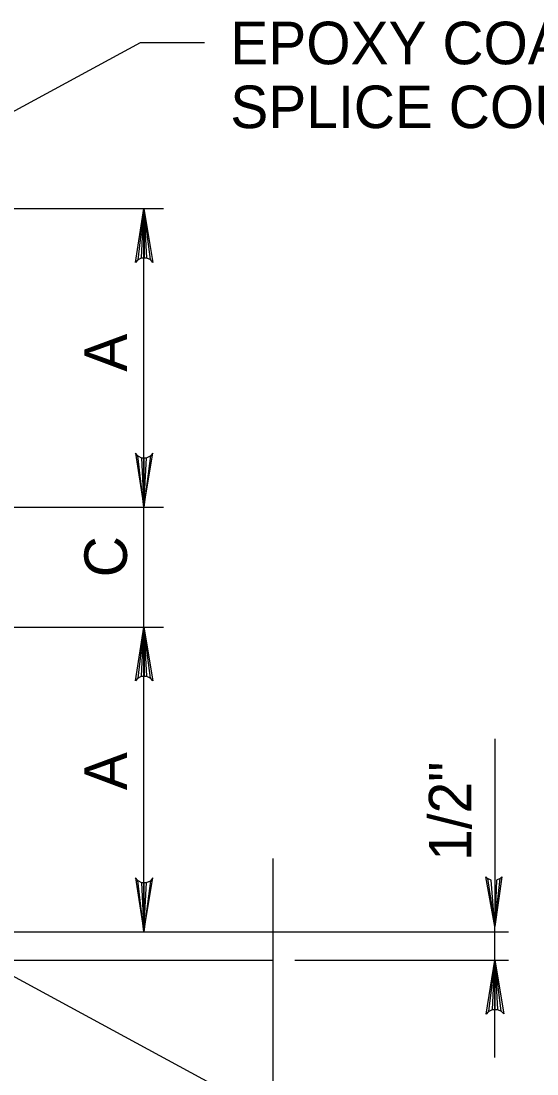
# Model space of a CAD drawing. Extents: x 641328 to 643024, y 298283 to 300065.
# Drawn here: x 641815.4 to 641851.7, y 298994.6 to 299068.8 of the extents above; entities that cross this region are included whole.
import ezdxf

# ---------------------------------------------------------------- set-up
doc = ezdxf.new("R2010")
doc.units = 0
doc.layers.add('2', color=7, linetype='Continuous')
doc.layers.add('40', color=7, linetype='Continuous')

msp = doc.modelspace()

# ---------------------------------------------------------------- linework, layer by layer
at = {"layer": '2'}
for p, q in [((641804.734, 299055.572), (641825.398, 299055.572)), ((641823.433, 299051.77), (641824.023, 299055.572)), ((641824.023, 299055.572), (641823.593, 299051.963)), ((641823.858, 299052.099), (641824.023, 299055.572)), ((641824.023, 299034.542), (641824.023, 299055.572)), ((641824.023, 299055.572), (641824.219, 299052.101)), ((641824.481, 299051.974), (641824.023, 299055.572)), ((641824.023, 299055.572), (641824.658, 299051.778)), ((641824.023, 299055.572), (641824.039, 299052.1)), ((641823.593, 299051.963), (641823.433, 299051.77)), ((641823.593, 299051.963), (641823.858, 299052.099)), ((641823.858, 299052.099), (641824.219, 299052.101)), ((641824.219, 299052.101), (641824.481, 299051.974)), ((641824.658, 299051.778), (641824.481, 299051.974)), ((641823.593, 299038.151), (641823.433, 299038.344)), ((641823.433, 299038.344), (641824.023, 299034.542)), ((641823.593, 299038.151), (641823.858, 299038.015)), ((641824.023, 299034.542), (641823.593, 299038.151)), ((641823.858, 299038.015), (641824.023, 299034.542)), ((641823.858, 299038.015), (641824.219, 299038.013)), ((641824.023, 299034.542), (641824.658, 299038.336)), ((641824.481, 299038.14), (641824.023, 299034.542)), ((641824.023, 299034.542), (641824.039, 299038.014)), ((641824.023, 299034.542), (641824.219, 299038.013)), ((641824.219, 299038.013), (641824.481, 299038.14)), ((641824.658, 299038.336), (641824.481, 299038.14)), ((641801.889, 299034.542), (641825.398, 299034.542)), ((641824.023, 299026.087), (641824.023, 299034.542)), ((641801.889, 299026.087), (641825.398, 299026.087)), ((641823.433, 299022.285), (641824.023, 299026.087)), ((641824.023, 299026.087), (641823.593, 299022.477)), ((641823.858, 299022.613), (641824.023, 299026.087)), ((641824.023, 299004.614), (641824.023, 299026.087)), ((641824.023, 299026.087), (641824.219, 299022.616)), ((641824.481, 299022.488), (641824.023, 299026.087)), ((641824.023, 299026.087), (641824.658, 299022.292)), ((641824.023, 299026.087), (641824.039, 299022.614)), ((641823.593, 299022.477), (641823.433, 299022.285)), ((641823.593, 299022.477), (641823.858, 299022.613)), ((641823.858, 299022.613), (641824.219, 299022.616)), ((641824.219, 299022.616), (641824.481, 299022.488)), ((641824.658, 299022.292), (641824.481, 299022.488)), ((641848.732, 299018.2), (641848.732, 299004.989)), ((641833.115, 299009.773), (641833.115, 298987.136)), ((641823.593, 299008.223), (641823.433, 299008.416)), ((641823.433, 299008.416), (641824.023, 299004.614)), ((641823.593, 299008.223), (641823.858, 299008.087)), ((641824.023, 299004.614), (641823.593, 299008.223)), ((641824.023, 299004.614), (641824.658, 299008.408)), ((641824.481, 299008.212), (641824.023, 299004.614)), ((641824.219, 299008.085), (641824.481, 299008.212)), ((641824.658, 299008.408), (641824.481, 299008.212)), ((641823.858, 299008.087), (641824.023, 299004.614)), ((641823.858, 299008.087), (641824.219, 299008.085)), ((641824.023, 299004.614), (641824.039, 299008.086)), ((641824.023, 299004.614), (641824.219, 299008.085)), ((641812.394, 299004.614), (641849.706, 299004.614)), ((641848.732, 298995.749), (641848.732, 299004.989)), ((641749.295, 299002.614), (641833.115, 299002.614)), ((641834.664, 299002.614), (641849.706, 299002.614)), ((641848.142, 298998.812), (641848.732, 299002.614)), ((641848.732, 299002.614), (641848.302, 298999.005)), ((641848.566, 298999.141), (641848.732, 299002.614)), ((641848.732, 299002.614), (641848.928, 298999.143)), ((641849.19, 298999.016), (641848.732, 299002.614)), ((641848.732, 299002.614), (641849.366, 298998.82)), ((641848.732, 299002.614), (641848.747, 298999.142)), ((641848.302, 298999.005), (641848.142, 298998.812)), ((641848.302, 298999.005), (641848.566, 298999.141)), ((641848.566, 298999.141), (641848.928, 298999.143)), ((641848.928, 298999.143), (641849.19, 298999.016)), ((641849.366, 298998.82), (641849.19, 298999.016))]:
    msp.add_line(p, q, dxfattribs=at)
for points in [[(641828.285, 299067.246), (641823.765, 299067.246), (641802.234, 299055.572)], [(641849.107, 299008.364), (641848.857, 299008.239), (641848.732, 299004.989), (641849.107, 299008.364), (641849.232, 299008.489), (641848.732, 299004.989), (641848.482, 299008.239), (641848.232, 299008.364), (641848.732, 299004.989), (641848.107, 299008.489), (641848.232, 299008.364)], [(641839.98, 298987.817), (641810.845, 299003.614)]]:
    msp.add_lwpolyline(points, dxfattribs=at)

# ---------------------------------------------------------------- texts
for s, p in [('EPOXY COATED GROUTED', (641830.109, 299065.738)), ('SPLICE COUPLER (TYP.)', (641830.109, 299061.238))]:
    msp.add_text(s, height=2.99999, dxfattribs=at).set_placement(p)
for s, p in [('A', (641822.833, 299044.077)), ('C', (641822.833, 299029.592)), ('A', (641822.833, 299014.591))]:
    msp.add_text(s, height=3, rotation=90, dxfattribs=at).set_placement(p)
at = {"layer": '40'}
msp.add_text('1/2"', height=3, rotation=90, dxfattribs=at).set_placement((641847.094, 299009.602))

doc.saveas('drawing.dxf')
